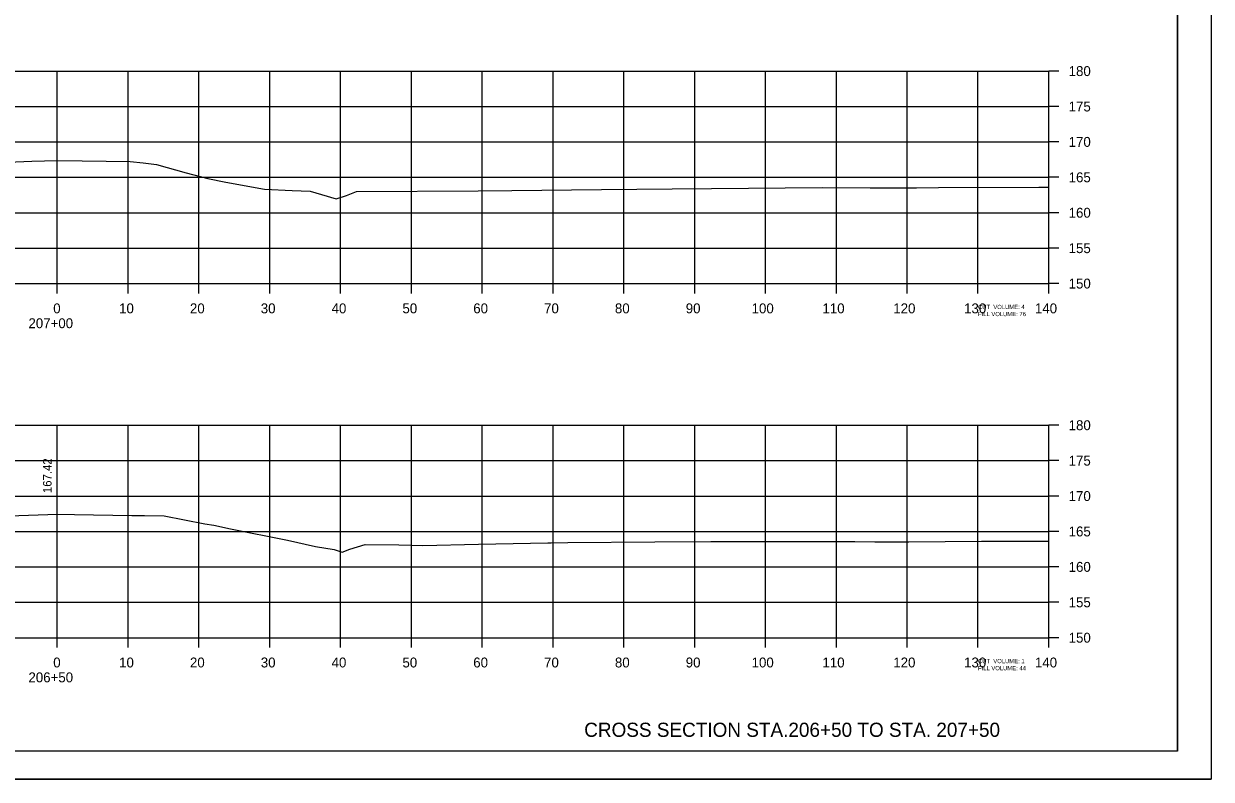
# Model space of a CAD drawing. Extents: x 1368503 to 1373085, y 379840 to 381833.
# Drawn here: x 1368668.3 to 1368836, y 380126 to 380232.7 of the extents above; entities that cross this region are included whole.
import ezdxf

# ---------------------------------------------------------------- set-up
doc = ezdxf.new("R2010")
doc.units = 0
for name, color, linetype in [('S_BRIDGE', 7, 'Continuous'), ('S_EDGE_PAVEMENT', 7, 'Continuous'), ('S_MISC_BOUNDARY', 7, 'Continuous'), ('S_PHOTO_CENTERS', 7, 'Continuous'), ('S_PHOTO_NOTES', 7, 'Continuous'), ('S_TRAILS', 7, 'Continuous'), ('S_TRAILS_ANNOT', 7, 'Continuous'), ('S_TREE', 7, 'Continuous')]:
    doc.layers.add(name, color=color, linetype=linetype)

msp = doc.modelspace()

# ---------------------------------------------------------------- linework, layer by layer
at = {"layer": 'S_BRIDGE'}
for q in [(1368831.24, 380335.49), (1368515.06, 380130.03)]:
    msp.add_line((1368831.24, 380130.03), q, dxfattribs=at)
at = {"layer": 'S_EDGE_PAVEMENT'}
for p, q in [((1368813.06, 380196.03), (1368813.06, 380226.03)), ((1368814.46, 380226.03), (1368813.06, 380226.03)), ((1368814.46, 380221.03), (1368813.06, 380221.03)), ((1368814.46, 380216.03), (1368813.06, 380216.03)), ((1368814.46, 380211.03), (1368813.06, 380211.03)), ((1368814.46, 380206.03), (1368813.06, 380206.03)), ((1368814.46, 380201.03), (1368813.06, 380201.03)), ((1368533.06, 380196.03), (1368813.06, 380196.03)), ((1368673.06, 380194.63), (1368673.06, 380196.03)), ((1368683.06, 380194.63), (1368683.06, 380196.03)), ((1368693.06, 380194.63), (1368693.06, 380196.03)), ((1368703.06, 380194.63), (1368703.06, 380196.03)), ((1368713.06, 380194.63), (1368713.06, 380196.03)), ((1368723.06, 380194.63), (1368723.06, 380196.03)), ((1368733.06, 380194.63), (1368733.06, 380196.03)), ((1368743.06, 380194.63), (1368743.06, 380196.03)), ((1368753.06, 380194.63), (1368753.06, 380196.03)), ((1368763.06, 380194.63), (1368763.06, 380196.03)), ((1368773.06, 380194.63), (1368773.06, 380196.03)), ((1368783.06, 380194.63), (1368783.06, 380196.03)), ((1368793.06, 380194.63), (1368793.06, 380196.03)), ((1368803.06, 380194.63), (1368803.06, 380196.03)), ((1368813.06, 380194.63), (1368813.06, 380196.03)), ((1368814.46, 380196.03), (1368813.06, 380196.03)), ((1368813.06, 380146.03), (1368813.06, 380176.03)), ((1368814.46, 380176.03), (1368813.06, 380176.03)), ((1368814.46, 380171.03), (1368813.06, 380171.03)), ((1368814.46, 380166.03), (1368813.06, 380166.03)), ((1368814.46, 380161.03), (1368813.06, 380161.03)), ((1368814.46, 380156.03), (1368813.06, 380156.03)), ((1368814.46, 380151.03), (1368813.06, 380151.03)), ((1368533.06, 380146.03), (1368813.06, 380146.03)), ((1368673.06, 380144.63), (1368673.06, 380146.03)), ((1368683.06, 380144.63), (1368683.06, 380146.03)), ((1368693.06, 380144.63), (1368693.06, 380146.03)), ((1368703.06, 380144.63), (1368703.06, 380146.03)), ((1368713.06, 380144.63), (1368713.06, 380146.03)), ((1368723.06, 380144.63), (1368723.06, 380146.03)), ((1368733.06, 380144.63), (1368733.06, 380146.03)), ((1368743.06, 380144.63), (1368743.06, 380146.03)), ((1368753.06, 380144.63), (1368753.06, 380146.03)), ((1368763.06, 380144.63), (1368763.06, 380146.03)), ((1368773.06, 380144.63), (1368773.06, 380146.03)), ((1368783.06, 380144.63), (1368783.06, 380146.03)), ((1368793.06, 380144.63), (1368793.06, 380146.03)), ((1368803.06, 380144.63), (1368803.06, 380146.03)), ((1368813.06, 380144.63), (1368813.06, 380146.03)), ((1368814.46, 380146.03), (1368813.06, 380146.03))]:
    msp.add_line(p, q, dxfattribs=at)
at = {"layer": 'S_MISC_BOUNDARY'}
for points in [[(1368662.61, 380213.05), (1368669.46, 380213.29), (1368673.03, 380213.41), (1368676.58, 380213.36), (1368683.34, 380213.27), (1368685.18, 380213.09), (1368687.09, 380212.85), (1368691.26, 380211.67), (1368694.32, 380210.85), (1368696.86, 380210.36), (1368702.34, 380209.38), (1368706.24, 380209.18), (1368708.79, 380209.07), (1368710.38, 380208.61), (1368712.44, 380207.98), (1368713.89, 380208.45), (1368715.3, 380209.02), (1368732.48, 380209.12), (1368737.25, 380209.17), (1368749.9, 380209.31), (1368759.89, 380209.42), (1368765.45, 380209.46), (1368781.07, 380209.58), (1368787.85, 380209.57), (1368794.38, 380209.55), (1368797.48, 380209.58), (1368811.64, 380209.62), (1368813.06, 380209.62)], [(1368664.85, 380163.19), (1368673.09, 380163.45), (1368675.51, 380163.41), (1368683.58, 380163.29), (1368685.4, 380163.27), (1368688.16, 380163.22), (1368693.9, 380162.13), (1368695.16, 380161.9), (1368697.53, 380161.42), (1368705.57, 380159.81), (1368709.54, 380158.9), (1368712.16, 380158.49), (1368713.28, 380158.09), (1368714.36, 380158.53), (1368716.52, 380159.2), (1368721.29, 380159.15), (1368724.7, 380159.06), (1368732.52, 380159.24), (1368742.35, 380159.42), (1368742.8, 380159.43), (1368745.17, 380159.45), (1368757.42, 380159.56), (1368765.33, 380159.6), (1368780.97, 380159.62), (1368785.68, 380159.6), (1368788.49, 380159.58), (1368791.98, 380159.58), (1368793.3, 380159.58), (1368803.57, 380159.64), (1368804.28, 380159.65), (1368813.06, 380159.68)]]:
    msp.add_lwpolyline(points, dxfattribs=at)
at = {"layer": 'S_PHOTO_CENTERS'}
for p, q in [((1368533.06, 380226.03), (1368813.06, 380226.03)), ((1368673.06, 380196.03), (1368673.06, 380226.03)), ((1368683.06, 380196.03), (1368683.06, 380226.03)), ((1368693.06, 380196.03), (1368693.06, 380226.03)), ((1368703.06, 380196.03), (1368703.06, 380226.03)), ((1368713.06, 380196.03), (1368713.06, 380226.03)), ((1368723.06, 380196.03), (1368723.06, 380226.03)), ((1368733.06, 380196.03), (1368733.06, 380226.03)), ((1368743.06, 380196.03), (1368743.06, 380226.03)), ((1368753.06, 380196.03), (1368753.06, 380226.03)), ((1368763.06, 380196.03), (1368763.06, 380226.03)), ((1368773.06, 380196.03), (1368773.06, 380226.03)), ((1368783.06, 380196.03), (1368783.06, 380226.03)), ((1368793.06, 380196.03), (1368793.06, 380226.03)), ((1368803.06, 380196.03), (1368803.06, 380226.03)), ((1368813.06, 380196.03), (1368813.06, 380226.03)), ((1368533.06, 380221.03), (1368813.06, 380221.03)), ((1368533.06, 380216.03), (1368813.06, 380216.03)), ((1368533.06, 380211.03), (1368813.06, 380211.03)), ((1368533.06, 380206.03), (1368813.06, 380206.03)), ((1368533.06, 380201.03), (1368813.06, 380201.03)), ((1368533.06, 380196.03), (1368813.06, 380196.03)), ((1368533.06, 380176.03), (1368813.06, 380176.03)), ((1368673.06, 380146.03), (1368673.06, 380176.03)), ((1368683.06, 380146.03), (1368683.06, 380176.03)), ((1368693.06, 380146.03), (1368693.06, 380176.03)), ((1368703.06, 380146.03), (1368703.06, 380176.03)), ((1368713.06, 380146.03), (1368713.06, 380176.03)), ((1368723.06, 380146.03), (1368723.06, 380176.03)), ((1368733.06, 380146.03), (1368733.06, 380176.03)), ((1368743.06, 380146.03), (1368743.06, 380176.03)), ((1368753.06, 380146.03), (1368753.06, 380176.03)), ((1368763.06, 380146.03), (1368763.06, 380176.03)), ((1368773.06, 380146.03), (1368773.06, 380176.03)), ((1368783.06, 380146.03), (1368783.06, 380176.03)), ((1368793.06, 380146.03), (1368793.06, 380176.03)), ((1368803.06, 380146.03), (1368803.06, 380176.03)), ((1368813.06, 380146.03), (1368813.06, 380176.03)), ((1368533.06, 380171.03), (1368813.06, 380171.03)), ((1368533.06, 380166.03), (1368813.06, 380166.03)), ((1368533.06, 380161.03), (1368813.06, 380161.03)), ((1368533.06, 380156.03), (1368813.06, 380156.03)), ((1368533.06, 380151.03), (1368813.06, 380151.03)), ((1368533.06, 380146.03), (1368813.06, 380146.03))]:
    msp.add_line(p, q, dxfattribs=at)
at = {"layer": 'S_PHOTO_NOTES'}
msp.add_line((1368502.66, 380126.05), (1368835.99, 380126.05), dxfattribs=at)
for points in [[(1368502.65, 380339.38), (1368835.99, 380339.38), (1368835.99, 380126.05), (1368502.65, 380126.05)], [(1368748.98, 380335.49), (1368748.98, 380325.61), (1368784.71, 380325.61), (1368784.71, 380322.69), (1368807.91, 380322.69), (1368807.91, 380298.36), (1368831.24, 380298.36), (1368831.24, 380130.03), (1368515.06, 380130.03), (1368515.06, 380335.49)]]:
    msp.add_lwpolyline(points, close=True, dxfattribs=at)

# ---------------------------------------------------------------- texts
at = {"layer": 'S_TRAILS'}
for s, height, p in [('180', 1.4, (1368815.86, 380225.33)), ('175', 1.4, (1368815.86, 380220.33)), ('170', 1.4, (1368815.86, 380215.33)), ('165', 1.4, (1368815.86, 380210.33)), ('160', 1.4, (1368815.86, 380205.33)), ('155', 1.4, (1368815.86, 380200.33)), ('150', 1.4, (1368815.86, 380195.33)), ('0', 1.4, (1368672.5, 380191.83)), ('10', 1.4, (1368681.8, 380191.83)), ('20', 1.4, (1368691.8, 380191.83)), ('30', 1.4, (1368701.8, 380191.83)), ('40', 1.4, (1368711.8, 380191.83)), ('50', 1.4, (1368721.8, 380191.83)), ('60', 1.4, (1368731.8, 380191.83)), ('70', 1.4, (1368741.8, 380191.83)), ('80', 1.4, (1368751.8, 380191.83)), ('90', 1.4, (1368761.8, 380191.83)), ('100', 1.4, (1368771.1, 380191.83)), ('110', 1.4, (1368781.1, 380191.83)), ('120', 1.4, (1368791.1, 380191.83)), ('130', 1.4, (1368801.1, 380191.83)), ('CUT  VOLUME: 4', 0.6, (1368803.06, 380192.43)), ('140', 1.4, (1368811.1, 380191.83)), ('207+00', 1.4, (1368669, 380189.73)), ('FILL VOLUME: 76', 0.6, (1368803.06, 380191.43)), ('180', 1.4, (1368815.86, 380175.33)), ('175', 1.4, (1368815.86, 380170.33)), ('170', 1.4, (1368815.86, 380165.33)), ('165', 1.4, (1368815.86, 380160.33)), ('160', 1.4, (1368815.86, 380155.33)), ('155', 1.4, (1368815.86, 380150.33)), ('150', 1.4, (1368815.86, 380145.33)), ('0', 1.4, (1368672.5, 380141.83)), ('10', 1.4, (1368681.8, 380141.83)), ('20', 1.4, (1368691.8, 380141.83)), ('30', 1.4, (1368701.8, 380141.83)), ('40', 1.4, (1368711.8, 380141.83)), ('50', 1.4, (1368721.8, 380141.83)), ('60', 1.4, (1368731.8, 380141.83)), ('70', 1.4, (1368741.8, 380141.83)), ('80', 1.4, (1368751.8, 380141.83)), ('90', 1.4, (1368761.8, 380141.83)), ('100', 1.4, (1368771.1, 380141.83)), ('110', 1.4, (1368781.1, 380141.83)), ('120', 1.4, (1368791.1, 380141.83)), ('130', 1.4, (1368801.1, 380141.83)), ('CUT  VOLUME: 1', 0.6, (1368803.06, 380142.43)), ('FILL VOLUME: 44', 0.6, (1368803.06, 380141.43)), ('140', 1.4, (1368811.1, 380141.83)), ('206+50', 1.4, (1368669, 380139.73))]:
    msp.add_text(s, height=height, dxfattribs=at).set_placement(p)
at = {"layer": 'S_TRAILS_ANNOT'}
msp.add_text('167.42', height=1.2, rotation=90, dxfattribs=at).set_placement((1368672.26, 380166.45))
at = {"layer": 'S_TREE'}
msp.add_text('CROSS SECTION STA.206+50 TO STA. 207+50', height=2, dxfattribs=at).set_placement((1368747.46, 380132.03))

doc.saveas('drawing.dxf')
